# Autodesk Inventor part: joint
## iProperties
Author: chr
Shininess: 20.0
Angle Display Precision: 2
Document Length Units: 11269
Document Angle Units: 11283
Document Time Units: 11279
Document Mass Units: 11290
Document Length Units Precision: 3
Document Angle Units Precision: 2
Compacted: False
PropertySet Name: _Private Model Information
Created: 2002-03
Part Number: joint
Material: Par défaut
Document SubType Name: Modélisation
Designer: chr
Control State: 0
Master: False
Checked Out: False
PropertySet Name: Design Tracking Control
Density: 0.0
Volumn: 0.0
Area: 0.0
PropertySet Name: Model Information
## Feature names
1. Balayage1
2. Balayage4
3. Extrusion1
4. Extrusion2
